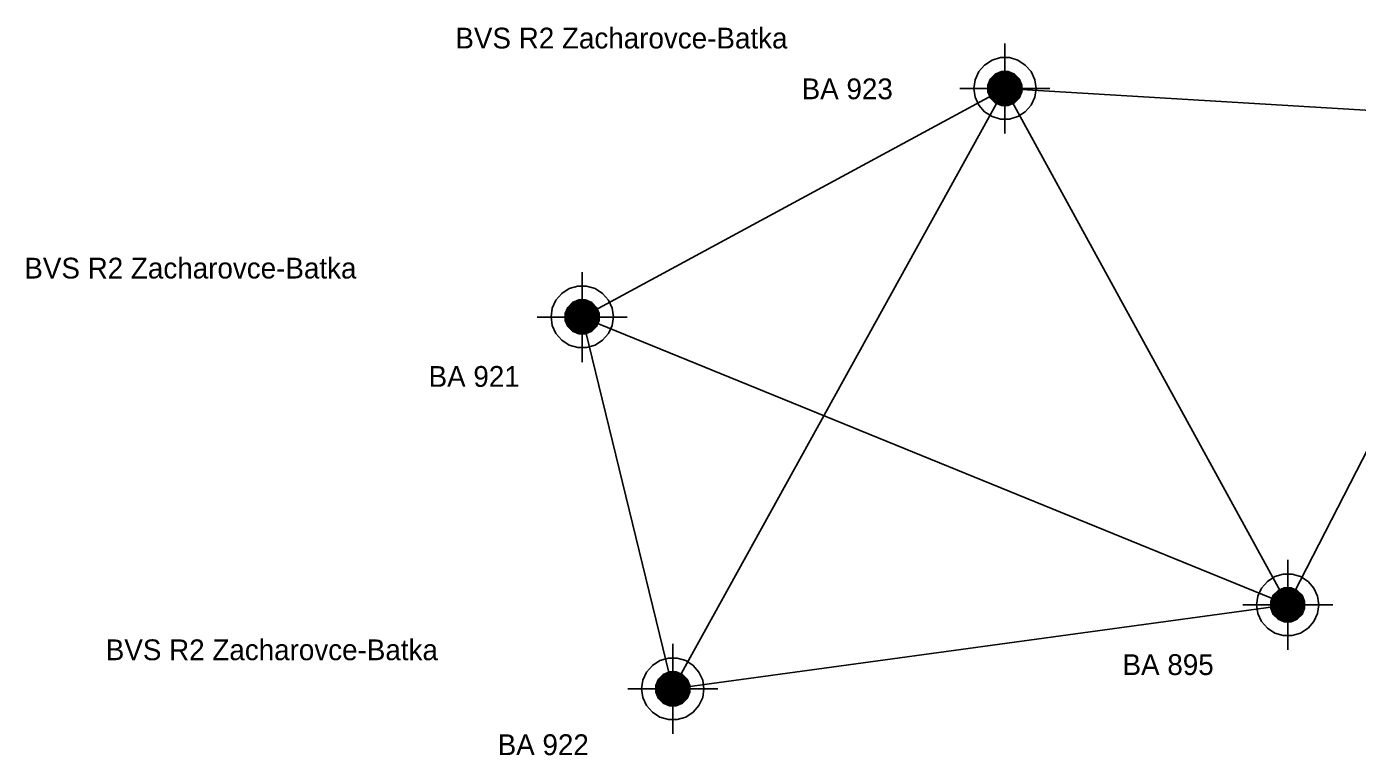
# Model space of a CAD drawing. Extents: x -346533 to -339969, y -1273090 to -1271585.
# Drawn here: x -346533.1 to -346052.9, y -1273090.4 to -1272827.3 of the extents above; entities that cross this region are included whole.
import ezdxf

# ---------------------------------------------------------------- set-up
doc = ezdxf.new("R2010")
doc.units = 0
for name, color, linetype in [('BP_11', 7, 'Continuous'), ('BP_12', 7, 'Continuous'), ('BP_14', 7, 'Continuous')]:
    doc.layers.add(name, color=color, linetype=linetype)

msp = doc.modelspace()

# ---------------------------------------------------------------- linework, layer by layer
at = {"layer": 'BP_11'}
for points in [[(-346180.05, -1272865.87), (-346180.05, -1272859.52), (-346180.05, -1272853.17), (-346180.05, -1272846.82), (-346180.05, -1272840.47), (-346180.05, -1272834.12), (-346180.05, -1272833.37)], [(-346180.05, -1272843.47), (-346178.85, -1272843.47), (-346176.6, -1272844.42), (-346174.9, -1272846.12), (-346173.95, -1272848.37), (-346173.95, -1272850.82), (-346174.9, -1272853.07), (-346176.6, -1272854.77), (-346178.85, -1272855.72), (-346181.3, -1272855.72), (-346183.55, -1272854.77), (-346185.25, -1272853.07), (-346186.2, -1272850.82), (-346186.2, -1272848.37), (-346185.25, -1272846.12), (-346183.55, -1272844.42), (-346181.3, -1272843.47), (-346180.1, -1272843.47), (-346178.3, -1272843.82), (-346181.9, -1272843.82), (-346182.7, -1272844.22), (-346177.5, -1272844.22), (-346176.7, -1272844.62), (-346183.05, -1272844.62), (-346183.5, -1272844.62), (-346183.9, -1272845.02), (-346177.55, -1272845.02), (-346176.3, -1272845.02), (-346175.9, -1272845.42), (-346182.25, -1272845.42), (-346184.3, -1272845.42), (-346184.7, -1272845.82), (-346178.35, -1272845.82), (-346175.5, -1272845.82), (-346175.1, -1272846.22), (-346181.45, -1272846.22), (-346185.1, -1272846.22), (-346185.1, -1272846.62), (-346178.75, -1272846.62), (-346175.1, -1272846.62), (-346174.7, -1272847.02), (-346181.05, -1272847.02), (-346185.5, -1272847.02), (-346185.5, -1272847.42), (-346179.15, -1272847.42), (-346174.7, -1272847.42), (-346174.7, -1272847.82), (-346181.05, -1272847.82), (-346185.5, -1272847.82), (-346185.9, -1272848.22), (-346179.55, -1272848.22), (-346174.3, -1272848.22), (-346174.3, -1272848.62), (-346180.65, -1272848.62), (-346185.9, -1272848.62), (-346185.9, -1272849.02), (-346179.55, -1272849.02), (-346174.3, -1272849.02), (-346174.3, -1272849.42), (-346180.65, -1272849.42), (-346185.9, -1272849.42), (-346185.9, -1272849.82), (-346179.55, -1272849.82), (-346174.3, -1272849.82), (-346174.3, -1272850.22), (-346180.65, -1272850.22), (-346185.9, -1272850.22), (-346185.9, -1272850.62), (-346179.55, -1272850.62), (-346174.3, -1272850.62), (-346174.3, -1272851.02), (-346180.65, -1272851.02), (-346185.9, -1272851.02), (-346185.9, -1272851.42), (-346179.55, -1272851.42), (-346174.3, -1272851.42), (-346174.7, -1272851.82), (-346181.05, -1272851.82), (-346185.5, -1272851.82), (-346185.5, -1272852.22), (-346179.15, -1272852.22), (-346174.7, -1272852.22), (-346175.1, -1272852.62), (-346181.45, -1272852.62), (-346185.1, -1272852.62), (-346185.1, -1272853.02), (-346178.75, -1272853.02), (-346175.1, -1272853.02), (-346175.5, -1272853.42), (-346181.85, -1272853.42), (-346184.7, -1272853.42), (-346184.3, -1272853.82), (-346177.95, -1272853.82), (-346175.9, -1272853.82), (-346176.3, -1272854.22), (-346182.65, -1272854.22), (-346183.9, -1272854.22), (-346183.5, -1272854.62), (-346177.15, -1272854.62), (-346176.7, -1272854.62)], [(-346196.3, -1272849.62), (-346189.95, -1272849.62), (-346183.6, -1272849.62), (-346177.25, -1272849.62), (-346170.9, -1272849.62), (-346164.55, -1272849.62), (-346163.8, -1272849.62)], [(-346176.7, -1272854.62), (-346177.5, -1272855.02), (-346182.7, -1272855.02), (-346181.9, -1272855.42), (-346178.3, -1272855.42)], [(-346332.61, -1272948.37), (-346332.61, -1272942.02), (-346332.61, -1272935.67), (-346332.61, -1272929.32), (-346332.61, -1272922.97), (-346332.61, -1272916.62), (-346332.61, -1272915.87)], [(-346332.61, -1272925.97), (-346331.41, -1272925.97), (-346329.16, -1272926.92), (-346327.46, -1272928.62), (-346326.51, -1272930.87), (-346326.51, -1272933.32), (-346327.46, -1272935.57), (-346329.16, -1272937.27), (-346331.41, -1272938.22), (-346333.86, -1272938.22), (-346336.11, -1272937.27), (-346337.81, -1272935.57), (-346338.76, -1272933.32), (-346338.76, -1272930.87), (-346337.81, -1272928.62), (-346336.11, -1272926.92), (-346333.86, -1272925.97), (-346332.66, -1272925.97), (-346330.86, -1272926.32), (-346334.46, -1272926.32), (-346335.26, -1272926.72), (-346330.06, -1272926.72), (-346329.26, -1272927.12), (-346335.61, -1272927.12), (-346336.06, -1272927.12), (-346336.46, -1272927.52), (-346330.11, -1272927.52), (-346328.86, -1272927.52), (-346328.46, -1272927.92), (-346334.81, -1272927.92), (-346336.86, -1272927.92), (-346337.26, -1272928.32), (-346330.91, -1272928.32), (-346328.06, -1272928.32), (-346327.66, -1272928.72), (-346334.01, -1272928.72), (-346337.66, -1272928.72), (-346337.66, -1272929.12), (-346331.31, -1272929.12), (-346327.66, -1272929.12), (-346327.26, -1272929.52), (-346333.61, -1272929.52), (-346338.06, -1272929.52), (-346338.06, -1272929.92), (-346331.71, -1272929.92), (-346327.26, -1272929.92), (-346327.26, -1272930.32), (-346333.61, -1272930.32), (-346338.06, -1272930.32), (-346338.46, -1272930.72), (-346332.11, -1272930.72), (-346326.86, -1272930.72), (-346326.86, -1272931.12), (-346333.21, -1272931.12), (-346338.46, -1272931.12), (-346338.46, -1272931.52), (-346332.11, -1272931.52), (-346326.86, -1272931.52), (-346326.86, -1272931.92), (-346333.21, -1272931.92), (-346338.46, -1272931.92), (-346338.46, -1272932.32), (-346332.11, -1272932.32), (-346326.86, -1272932.32), (-346326.86, -1272932.72), (-346333.21, -1272932.72), (-346338.46, -1272932.72), (-346338.46, -1272933.12), (-346332.11, -1272933.12), (-346326.86, -1272933.12), (-346326.86, -1272933.52), (-346333.21, -1272933.52), (-346338.46, -1272933.52), (-346338.46, -1272933.92), (-346332.11, -1272933.92), (-346326.86, -1272933.92), (-346327.26, -1272934.32), (-346333.61, -1272934.32), (-346338.06, -1272934.32), (-346338.06, -1272934.72), (-346331.71, -1272934.72), (-346327.26, -1272934.72), (-346327.66, -1272935.12), (-346334.01, -1272935.12), (-346337.66, -1272935.12), (-346337.66, -1272935.52), (-346331.31, -1272935.52), (-346327.66, -1272935.52), (-346328.06, -1272935.92), (-346334.41, -1272935.92), (-346337.26, -1272935.92), (-346336.86, -1272936.32), (-346330.51, -1272936.32), (-346328.46, -1272936.32), (-346328.86, -1272936.72), (-346335.21, -1272936.72), (-346336.46, -1272936.72), (-346336.06, -1272937.12), (-346329.71, -1272937.12), (-346329.26, -1272937.12)], [(-346348.86, -1272932.12), (-346342.51, -1272932.12), (-346336.16, -1272932.12), (-346329.81, -1272932.12), (-346323.46, -1272932.12), (-346317.11, -1272932.12), (-346316.36, -1272932.12)], [(-346329.26, -1272937.12), (-346330.06, -1272937.52), (-346335.26, -1272937.52), (-346334.46, -1272937.92), (-346330.86, -1272937.92)], [(-346078.01, -1273052.32), (-346078.01, -1273045.97), (-346078.01, -1273039.62), (-346078.01, -1273033.27), (-346078.01, -1273026.92), (-346078.01, -1273020.57), (-346078.01, -1273019.82)], [(-346078.01, -1273029.92), (-346076.81, -1273029.92), (-346074.56, -1273030.87), (-346072.86, -1273032.57), (-346071.91, -1273034.82), (-346071.91, -1273037.27), (-346072.86, -1273039.52), (-346074.56, -1273041.22), (-346076.81, -1273042.17), (-346079.26, -1273042.17), (-346081.51, -1273041.22), (-346083.21, -1273039.52), (-346084.16, -1273037.27), (-346084.16, -1273034.82), (-346083.21, -1273032.57), (-346081.51, -1273030.87), (-346079.26, -1273029.92), (-346078.06, -1273029.92), (-346076.26, -1273030.27), (-346079.86, -1273030.27), (-346080.66, -1273030.67), (-346075.46, -1273030.67), (-346074.66, -1273031.07), (-346081.01, -1273031.07), (-346081.46, -1273031.07), (-346081.86, -1273031.47), (-346075.51, -1273031.47), (-346074.26, -1273031.47), (-346073.86, -1273031.87), (-346080.21, -1273031.87), (-346082.26, -1273031.87), (-346082.66, -1273032.27), (-346076.31, -1273032.27), (-346073.46, -1273032.27), (-346073.06, -1273032.67), (-346079.41, -1273032.67), (-346083.06, -1273032.67), (-346083.06, -1273033.07), (-346076.71, -1273033.07), (-346073.06, -1273033.07), (-346072.66, -1273033.47), (-346079.01, -1273033.47), (-346083.46, -1273033.47), (-346083.46, -1273033.87), (-346077.11, -1273033.87), (-346072.66, -1273033.87), (-346072.66, -1273034.27), (-346079.01, -1273034.27), (-346083.46, -1273034.27), (-346083.86, -1273034.67), (-346077.51, -1273034.67), (-346072.26, -1273034.67), (-346072.26, -1273035.07), (-346078.61, -1273035.07), (-346083.86, -1273035.07), (-346083.86, -1273035.47), (-346077.51, -1273035.47), (-346072.26, -1273035.47), (-346072.26, -1273035.87), (-346078.61, -1273035.87), (-346083.86, -1273035.87), (-346083.86, -1273036.27), (-346077.51, -1273036.27), (-346072.26, -1273036.27), (-346072.26, -1273036.67), (-346078.61, -1273036.67), (-346083.86, -1273036.67), (-346083.86, -1273037.07), (-346077.51, -1273037.07), (-346072.26, -1273037.07), (-346072.26, -1273037.47), (-346078.61, -1273037.47), (-346083.86, -1273037.47), (-346083.86, -1273037.87), (-346077.51, -1273037.87), (-346072.26, -1273037.87), (-346072.66, -1273038.27), (-346079.01, -1273038.27), (-346083.46, -1273038.27), (-346083.46, -1273038.67), (-346077.11, -1273038.67), (-346072.66, -1273038.67), (-346073.06, -1273039.07), (-346079.41, -1273039.07), (-346083.06, -1273039.07), (-346083.06, -1273039.47), (-346076.71, -1273039.47), (-346073.06, -1273039.47), (-346073.46, -1273039.87), (-346079.81, -1273039.87), (-346082.66, -1273039.87), (-346082.26, -1273040.27), (-346075.91, -1273040.27), (-346073.86, -1273040.27), (-346074.26, -1273040.67), (-346080.61, -1273040.67), (-346081.86, -1273040.67), (-346081.46, -1273041.07), (-346075.11, -1273041.07), (-346074.66, -1273041.07)], [(-346094.26, -1273036.07), (-346087.91, -1273036.07), (-346081.56, -1273036.07), (-346075.21, -1273036.07), (-346068.86, -1273036.07), (-346062.51, -1273036.07), (-346061.76, -1273036.07)], [(-346074.66, -1273041.07), (-346075.46, -1273041.47), (-346080.66, -1273041.47), (-346079.86, -1273041.87), (-346076.26, -1273041.87)], [(-346299.91, -1273082.65), (-346299.91, -1273076.3), (-346299.91, -1273069.95), (-346299.91, -1273063.6), (-346299.91, -1273057.25), (-346299.91, -1273050.9), (-346299.91, -1273050.15)], [(-346299.91, -1273060.25), (-346298.71, -1273060.25), (-346296.46, -1273061.2), (-346294.76, -1273062.9), (-346293.81, -1273065.15), (-346293.81, -1273067.6), (-346294.76, -1273069.85), (-346296.46, -1273071.55), (-346298.71, -1273072.5), (-346301.16, -1273072.5), (-346303.41, -1273071.55), (-346305.11, -1273069.85), (-346306.06, -1273067.6), (-346306.06, -1273065.15), (-346305.11, -1273062.9), (-346303.41, -1273061.2), (-346301.16, -1273060.25), (-346299.96, -1273060.25), (-346298.16, -1273060.6), (-346301.76, -1273060.6), (-346302.56, -1273061), (-346297.36, -1273061), (-346296.56, -1273061.4), (-346302.91, -1273061.4), (-346303.36, -1273061.4), (-346303.76, -1273061.8), (-346297.41, -1273061.8), (-346296.16, -1273061.8), (-346295.76, -1273062.2), (-346302.11, -1273062.2), (-346304.16, -1273062.2), (-346304.56, -1273062.6), (-346298.21, -1273062.6), (-346295.36, -1273062.6), (-346294.96, -1273063), (-346301.31, -1273063), (-346304.96, -1273063), (-346304.96, -1273063.4), (-346298.61, -1273063.4), (-346294.96, -1273063.4), (-346294.56, -1273063.8), (-346300.91, -1273063.8), (-346305.36, -1273063.8), (-346305.36, -1273064.2), (-346299.01, -1273064.2), (-346294.56, -1273064.2), (-346294.56, -1273064.6), (-346300.91, -1273064.6), (-346305.36, -1273064.6), (-346305.76, -1273065), (-346299.41, -1273065), (-346294.16, -1273065), (-346294.16, -1273065.4), (-346300.51, -1273065.4), (-346305.76, -1273065.4), (-346305.76, -1273065.8), (-346299.41, -1273065.8), (-346294.16, -1273065.8), (-346294.16, -1273066.2), (-346300.51, -1273066.2), (-346305.76, -1273066.2), (-346305.76, -1273066.6), (-346299.41, -1273066.6), (-346294.16, -1273066.6), (-346294.16, -1273067), (-346300.51, -1273067), (-346305.76, -1273067), (-346305.76, -1273067.4), (-346299.41, -1273067.4), (-346294.16, -1273067.4), (-346294.16, -1273067.8), (-346300.51, -1273067.8), (-346305.76, -1273067.8), (-346305.76, -1273068.2), (-346299.41, -1273068.2), (-346294.16, -1273068.2), (-346294.56, -1273068.6), (-346300.91, -1273068.6), (-346305.36, -1273068.6), (-346305.36, -1273069), (-346299.01, -1273069), (-346294.56, -1273069), (-346294.96, -1273069.4), (-346301.31, -1273069.4), (-346304.96, -1273069.4), (-346304.96, -1273069.8), (-346298.61, -1273069.8), (-346294.96, -1273069.8), (-346295.36, -1273070.2), (-346301.71, -1273070.2), (-346304.56, -1273070.2), (-346304.16, -1273070.6), (-346297.81, -1273070.6), (-346295.76, -1273070.6), (-346296.16, -1273071), (-346302.51, -1273071), (-346303.76, -1273071), (-346303.36, -1273071.4), (-346297.01, -1273071.4), (-346296.56, -1273071.4)], [(-346316.16, -1273066.4), (-346309.81, -1273066.4), (-346303.46, -1273066.4), (-346297.11, -1273066.4), (-346290.76, -1273066.4), (-346284.41, -1273066.4), (-346283.66, -1273066.4)], [(-346296.56, -1273071.4), (-346297.36, -1273071.8), (-346302.56, -1273071.8), (-346301.76, -1273072.2), (-346298.16, -1273072.2)]]:
    msp.add_lwpolyline(points, dxfattribs=at)
for points in [[(-346178.45, -1272838.47), (-346175.4, -1272839.37), (-346172.7, -1272841.12), (-346170.6, -1272843.52), (-346169.25, -1272846.42), (-346168.8, -1272849.57), (-346169.25, -1272852.72), (-346170.6, -1272855.62), (-346172.7, -1272858.02), (-346175.4, -1272859.77), (-346178.45, -1272860.67), (-346181.65, -1272860.67), (-346184.7, -1272859.77), (-346187.4, -1272858.02), (-346189.5, -1272855.62), (-346190.85, -1272852.72), (-346191.3, -1272849.57), (-346190.85, -1272846.42), (-346189.5, -1272843.52), (-346187.4, -1272841.12), (-346184.7, -1272839.37), (-346181.65, -1272838.47)], [(-346331.01, -1272920.97), (-346327.96, -1272921.87), (-346325.26, -1272923.62), (-346323.16, -1272926.02), (-346321.81, -1272928.92), (-346321.36, -1272932.07), (-346321.81, -1272935.22), (-346323.16, -1272938.12), (-346325.26, -1272940.52), (-346327.96, -1272942.27), (-346331.01, -1272943.17), (-346334.21, -1272943.17), (-346337.26, -1272942.27), (-346339.96, -1272940.52), (-346342.06, -1272938.12), (-346343.41, -1272935.22), (-346343.86, -1272932.07), (-346343.41, -1272928.92), (-346342.06, -1272926.02), (-346339.96, -1272923.62), (-346337.26, -1272921.87), (-346334.21, -1272920.97)], [(-346076.41, -1273024.92), (-346073.36, -1273025.82), (-346070.66, -1273027.57), (-346068.56, -1273029.97), (-346067.21, -1273032.87), (-346066.76, -1273036.02), (-346067.21, -1273039.17), (-346068.56, -1273042.07), (-346070.66, -1273044.47), (-346073.36, -1273046.22), (-346076.41, -1273047.12), (-346079.61, -1273047.12), (-346082.66, -1273046.22), (-346085.36, -1273044.47), (-346087.46, -1273042.07), (-346088.81, -1273039.17), (-346089.26, -1273036.02), (-346088.81, -1273032.87), (-346087.46, -1273029.97), (-346085.36, -1273027.57), (-346082.66, -1273025.82), (-346079.61, -1273024.92)], [(-346298.31, -1273055.25), (-346295.26, -1273056.15), (-346292.56, -1273057.9), (-346290.46, -1273060.3), (-346289.11, -1273063.2), (-346288.66, -1273066.35), (-346289.11, -1273069.5), (-346290.46, -1273072.4), (-346292.56, -1273074.8), (-346295.26, -1273076.55), (-346298.31, -1273077.45), (-346301.51, -1273077.45), (-346304.56, -1273076.55), (-346307.26, -1273074.8), (-346309.36, -1273072.4), (-346310.71, -1273069.5), (-346311.16, -1273066.35), (-346310.71, -1273063.2), (-346309.36, -1273060.3), (-346307.26, -1273057.9), (-346304.56, -1273056.15), (-346301.51, -1273055.25)]]:
    msp.add_lwpolyline(points, close=True, dxfattribs=at)
at = {"layer": 'BP_14'}
for p, q in [((-346180.05, -1272849.62), (-346332.61, -1272932.12)), ((-346299.91, -1273066.4), (-346180.05, -1272849.62)), ((-345988.21, -1272861.12), (-346180.05, -1272849.62)), ((-346180.05, -1272849.62), (-346078.01, -1273036.07)), ((-346078.01, -1273036.07), (-345988.21, -1272861.12)), ((-346332.61, -1272932.12), (-346299.91, -1273066.4)), ((-346078.01, -1273036.07), (-346332.61, -1272932.12)), ((-346299.91, -1273066.4), (-346078.01, -1273036.07))]:
    msp.add_line(p, q, dxfattribs=at)

# ---------------------------------------------------------------- texts
at = {"layer": 'BP_12'}
for s, p in [('BVS R2 Zacharovce-Batka', (-346378.37, -1272835.15)), ('BA 923', (-346253.41, -1272853.48)), ('BVS R2 Zacharovce-Batka', (-346533.91, -1272918.21)), ('BA 921', (-346388.04, -1272957.32)), ('BVS R2 Zacharovce-Batka', (-346504.52, -1273056.03)), ('BA 895', (-346137.62, -1273061.38)), ('BA 922', (-346363.11, -1273090.29))]:
    msp.add_text(s, height=7.5, dxfattribs=at).set_placement(p)

doc.saveas('drawing.dxf')
